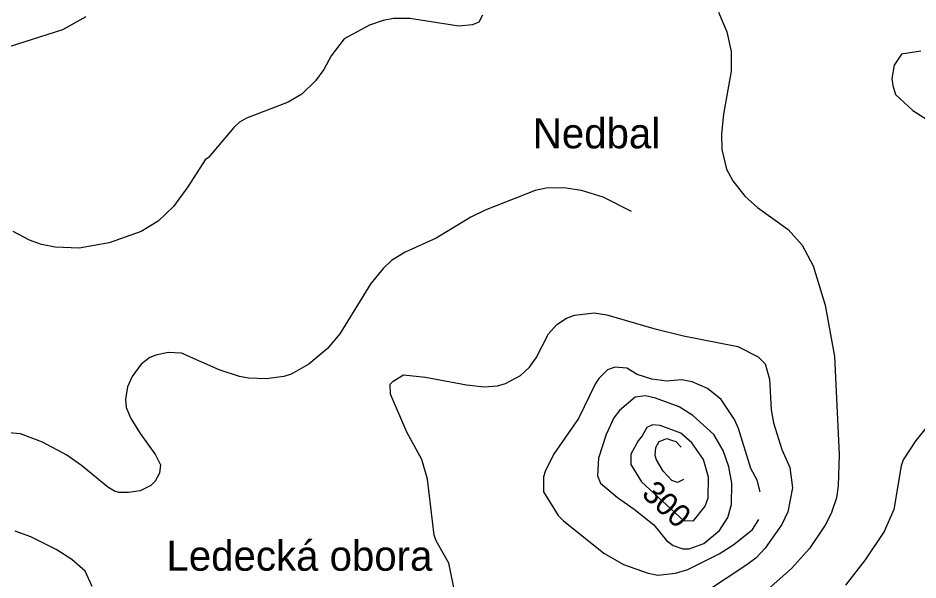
# Model space of a CAD drawing. Extents: x -662620 to -656370, y -1067090 to -1062990.
# Drawn here: x -662202 to -661678, y -1066171 to -1065844 of the extents above; entities that cross this region are included whole.
import ezdxf

# ---------------------------------------------------------------- set-up
doc = ezdxf.new("R2010")
doc.units = 0
for name, color, linetype in [('HRANICE_KATASTRÁLNÍHO_ÚZEMÍ', 7, 'Continuous'), ('MÍSTNÍ_NÁZVY', 7, 'Continuous'), ('VRSTEVNICE_ZDŮRAZNĚNÁ', 7, 'Continuous'), ('VRSTEVNICE_ZDŮRAZNĚNÁ_-_POPIS', 7, 'Continuous'), ('VRSTEVNICE_ZÁKLADNÍ', 7, 'Continuous')]:
    doc.layers.add(name, color=color, linetype=linetype)

msp = doc.modelspace()

# ---------------------------------------------------------------- linework, layer by layer
at = {"layer": 'HRANICE_KATASTRÁLNÍHO_ÚZEMÍ'}
msp.add_lwpolyline([(-662220.38, -1065864.43), (-662176.37, -1065850.47), (-662162.75, -1065842.94)], dxfattribs=at)
at = {"layer": 'VRSTEVNICE_ZDŮRAZNĚNÁ'}
for points in [[(-661676.86, -1065863.15), (-661687.99, -1065864.87), (-661692.27, -1065871.29), (-661693.56, -1065879), (-661693.13, -1065882.99), (-661691.56, -1065888.28)], [(-661691.56, -1065888.28), (-661681.42, -1065897.55), (-661661.58, -1065910.26)], [(-661670.29, -1066078.26), (-661679.71, -1066089.68), (-661686.99, -1066101.1), (-661688.13, -1066104.52), (-661692.56, -1066129.93), (-661698.12, -1066142.78), (-661709.26, -1066159.19), (-661720.68, -1066173.89)], [(-661800.47, -1066111.09), (-661803.32, -1066100.81), (-661810.17, -1066091.11), (-661816.45, -1066085.54), (-661828.44, -1066081.11), (-661833.01, -1066080.54), (-661836.34, -1066082.2), (-661839.01, -1066086.97), (-661841.43, -1066089.96), (-661845.57, -1066097.67), (-661845.57, -1066103.81), (-661839.44, -1066113.8), (-661814.88, -1066136.35), (-661809.11, -1066136.61), (-661802.32, -1066127.93), (-661800.61, -1066123.08), (-661800.47, -1066111.09)]]:
    msp.add_lwpolyline(points, dxfattribs=at)
at = {"layer": 'VRSTEVNICE_ZÁKLADNÍ'}
for points in [[(-661931.97, -1065842.23), (-661934.08, -1065846.14), (-661937.78, -1065847.83), (-661945.7, -1065848.46), (-661974.32, -1065844.17), (-661983.74, -1065844.03), (-661989.74, -1065845.17), (-661997.73, -1065848.02), (-662012.43, -1065855.87), (-662020, -1065865.87), (-662024.42, -1065873.86), (-662029.28, -1065880.43), (-662037.13, -1065888.13), (-662045.12, -1065892.84), (-662069.39, -1065902.12), (-662073.38, -1065904.41), (-662076.81, -1065907.55), (-662091.51, -1065924.96), (-662093.51, -1065926.39), (-662103.5, -1065942.09), (-662111.78, -1065953.51), (-662120.77, -1065962.07), (-662130.76, -1065968.07), (-662149.32, -1065974.63), (-662166.73, -1065977.77), (-662180.72, -1065977.2), (-662188.71, -1065975.63), (-662195.71, -1065973.21), (-662205.27, -1065968.07)], [(-661794.61, -1065840.46), (-661789.76, -1065851.88), (-661787.19, -1065863.3), (-661787.19, -1065874.72), (-661791.62, -1065899.84), (-661792.9, -1065911.26), (-661792.62, -1065920.39), (-661789.9, -1065931.81), (-661786.19, -1065938.66), (-661779.2, -1065947.51), (-661771.78, -1065954.08), (-661753.93, -1065966.92), (-661745.94, -1065976.06), (-661739.52, -1065988.05), (-661732.52, -1066010.89), (-661727.12, -1066040.89), (-661724.25, -1066097.96), (-661724.82, -1066116.23), (-661725.96, -1066123.08), (-661728.95, -1066132.21), (-661732.38, -1066139.07), (-661741.52, -1066152.63), (-661752.08, -1066164.33), (-661772.21, -1066182.17)], [(-661794.61, -1065840.46), (-661789.76, -1065851.88), (-661787.19, -1065863.3), (-661787.19, -1065874.72), (-661791.62, -1065899.84), (-661792.9, -1065911.26), (-661792.62, -1065920.39), (-661789.9, -1065931.81), (-661786.19, -1065938.66), (-661779.2, -1065947.51), (-661771.78, -1065954.08), (-661753.93, -1065966.92), (-661745.94, -1065976.06), (-661739.52, -1065988.05), (-661732.52, -1066010.89), (-661727.12, -1066040.89), (-661724.25, -1066097.96), (-661724.82, -1066116.23), (-661725.96, -1066123.08), (-661728.95, -1066132.21), (-661732.38, -1066139.07), (-661741.52, -1066152.63), (-661752.08, -1066164.33), (-661772.21, -1066182.17)], [(-661845.28, -1065956.37), (-661861.74, -1065948.03), (-661874.41, -1065944.23), (-661884.68, -1065942.66), (-661894.96, -1065942.95), (-661901.24, -1065944.23), (-661930.36, -1065955.65), (-661938.78, -1065959.79), (-661958.91, -1065972.06), (-661976.89, -1065980.06), (-661984.88, -1065985.05), (-661989.74, -1065989.62), (-661997.02, -1065998.33), (-662015, -1066027.59), (-662022.28, -1066036.15), (-662033.13, -1066045.29), (-662043.41, -1066051.14), (-662047.69, -1066052.57), (-662057.97, -1066053.85), (-662068.24, -1066053.42), (-662073.38, -1066052.57), (-662085.37, -1066048.57), (-662107.21, -1066038.87), (-662114.89, -1066038.53), (-662122.2, -1066040.01), (-662125.62, -1066041.43), (-662130.62, -1066045.29), (-662135.9, -1066052.43), (-662138.61, -1066058.56), (-662139.9, -1066065.7), (-662139.33, -1066070.55), (-662136.76, -1066076.98), (-662131.33, -1066085.68), (-662122.34, -1066098.1), (-662119.34, -1066103.95), (-662120.06, -1066108.81), (-662122.48, -1066113.37), (-662125.05, -1066115.94), (-662131.18, -1066119.06), (-662138.14, -1066120.12), (-662143.61, -1066119.94), (-662146.18, -1066119.23), (-662150.03, -1066116.94), (-662165.45, -1066104.24), (-662174.01, -1066098.24), (-662188.14, -1066090.68), (-662200.99, -1066085.97), (-662217.26, -1066084.54)], [(-661946.34, -1066186.6), (-661951.48, -1066161.19), (-661958.91, -1066148.2), (-661960.19, -1066144.78), (-661964.05, -1066112.23), (-661967.19, -1066100.81), (-661976.04, -1066084.83), (-661985.46, -1066062.84), (-661985.74, -1066056.99), (-661984.03, -1066055.14), (-661977.91, -1066051.61), (-661965.19, -1066052.85), (-661941.21, -1066057.28), (-661930.93, -1066058.56), (-661923.22, -1066057.99), (-661918.65, -1066056.56), (-661909.81, -1066051.85), (-661904.67, -1066047.14), (-661900.67, -1066041.72), (-661893.53, -1066027.73), (-661888.68, -1066022.31), (-661882.97, -1066018.6), (-661878.4, -1066016.88), (-661866.98, -1066015.46), (-661859.56, -1066016.6), (-661832.16, -1066024.59), (-661815.03, -1066028.87), (-661783.34, -1066035.01)], [(-661946.34, -1066186.6), (-661951.48, -1066161.19), (-661958.91, -1066148.2), (-661960.19, -1066144.78), (-661964.05, -1066112.23), (-661967.19, -1066100.81), (-661976.04, -1066084.83), (-661985.46, -1066062.84), (-661985.74, -1066056.99), (-661984.03, -1066055.14), (-661977.91, -1066051.61), (-661965.19, -1066052.85), (-661941.21, -1066057.28), (-661930.93, -1066058.56), (-661923.22, -1066057.99), (-661918.65, -1066056.56), (-661909.81, -1066051.85), (-661904.67, -1066047.14), (-661900.67, -1066041.72), (-661893.53, -1066027.73), (-661888.68, -1066022.31), (-661882.97, -1066018.6), (-661878.4, -1066016.88), (-661866.98, -1066015.46), (-661859.56, -1066016.6), (-661832.16, -1066024.59), (-661815.03, -1066028.87), (-661783.34, -1066035.01)], [(-661783.34, -1066035.01), (-661771.49, -1066041), (-661767.35, -1066045.14), (-661764.78, -1066054.14), (-661763.93, -1066071.98), (-661762.5, -1066079.4), (-661757.65, -1066094.96), (-661752.94, -1066105.38), (-661751.51, -1066117.37), (-661754.22, -1066131.36), (-661757.79, -1066138.64), (-661767.35, -1066152.34), (-661772.92, -1066158.19), (-661778.63, -1066162.47), (-661801.61, -1066177.61)], [(-661783.34, -1066035.01), (-661771.49, -1066041), (-661767.35, -1066045.14), (-661764.78, -1066054.14), (-661763.93, -1066071.98), (-661762.5, -1066079.4), (-661757.65, -1066094.96), (-661752.94, -1066105.38), (-661751.51, -1066117.37), (-661754.22, -1066131.36), (-661757.79, -1066138.64), (-661767.35, -1066152.34), (-661772.92, -1066158.19), (-661778.63, -1066162.47), (-661801.61, -1066177.61)], [(-661770.22, -1066119.59), (-661772.01, -1066112.94), (-661775.71, -1066105.98), (-661782.91, -1066082.83), (-661785.34, -1066077.55), (-661793.03, -1066065.79), (-661801.04, -1066059.42), (-661809.89, -1066055.56), (-661816.17, -1066054.42), (-661824.73, -1066055.28), (-661833.3, -1066054.14), (-661841.86, -1066051.42), (-661848, -1066047.57), (-661854.99, -1066047), (-661859.28, -1066048.71), (-661864.27, -1066053.57), (-661866.27, -1066056.56), (-661876.12, -1066076.98), (-661890.25, -1066097.24), (-661895.25, -1066107.24), (-661896.39, -1066110.95), (-661896.53, -1066119.65), (-661887.82, -1066133.36), (-661884.83, -1066136.5), (-661861.27, -1066155.34), (-661849.86, -1066161.9), (-661835.58, -1066167.04), (-661829.87, -1066168.18), (-661819.59, -1066167.04), (-661812.46, -1066164.9), (-661794.19, -1066155.77), (-661785.62, -1066150.34), (-661774.77, -1066141.64), (-661771.06, -1066135.78)], [(-661770.22, -1066119.59), (-661772.01, -1066112.94), (-661775.71, -1066105.98), (-661782.91, -1066082.83), (-661785.34, -1066077.55), (-661793.03, -1066065.79), (-661801.04, -1066059.42), (-661809.89, -1066055.56), (-661816.17, -1066054.42), (-661824.73, -1066055.28), (-661833.3, -1066054.14), (-661841.86, -1066051.42), (-661848, -1066047.57), (-661854.99, -1066047), (-661859.28, -1066048.71), (-661864.27, -1066053.57), (-661866.27, -1066056.56), (-661876.12, -1066076.98), (-661890.25, -1066097.24), (-661895.25, -1066107.24), (-661896.39, -1066110.95), (-661896.53, -1066119.65), (-661887.82, -1066133.36), (-661884.83, -1066136.5), (-661861.27, -1066155.34), (-661849.86, -1066161.9), (-661835.58, -1066167.04), (-661829.87, -1066168.18), (-661819.59, -1066167.04), (-661812.46, -1066164.9), (-661794.19, -1066155.77), (-661785.62, -1066150.34), (-661774.77, -1066141.64), (-661771.06, -1066135.78)], [(-661809.46, -1066075.26), (-661817.45, -1066070.12), (-661831.3, -1066065.13), (-661837.01, -1066063.7), (-661843, -1066064.56), (-661852.14, -1066072.26), (-661855.42, -1066076.55), (-661859.99, -1066086.25), (-661864.41, -1066099.96), (-661864.98, -1066110.23), (-661863.27, -1066114.52), (-661853.42, -1066122.94), (-661843.57, -1066129.65), (-661832.16, -1066138.92), (-661824.88, -1066148.06), (-661821.02, -1066150.91), (-661815.31, -1066152.77), (-661811.6, -1066152.77), (-661803.18, -1066149.63), (-661794.04, -1066142.06), (-661789.19, -1066134.5), (-661787.05, -1066127.08), (-661786.76, -1066114.52), (-661788.48, -1066105.09), (-661791.76, -1066095.67), (-661797.33, -1066086.25), (-661809.46, -1066075.26)], [(-661809.46, -1066075.26), (-661817.45, -1066070.12), (-661831.3, -1066065.13), (-661837.01, -1066063.7), (-661843, -1066064.56), (-661852.14, -1066072.26), (-661855.42, -1066076.55), (-661859.99, -1066086.25), (-661864.41, -1066099.96), (-661864.98, -1066110.23), (-661863.27, -1066114.52), (-661853.42, -1066122.94), (-661843.57, -1066129.65), (-661832.16, -1066138.92), (-661824.88, -1066148.06), (-661821.02, -1066150.91), (-661815.31, -1066152.77), (-661811.6, -1066152.77), (-661803.18, -1066149.63), (-661794.04, -1066142.06), (-661789.19, -1066134.5), (-661787.05, -1066127.08), (-661786.76, -1066114.52), (-661788.48, -1066105.09), (-661791.76, -1066095.67), (-661797.33, -1066086.25), (-661809.46, -1066075.26)], [(-661815.02, -1066112.44), (-661818.5, -1066114.13), (-661821.78, -1066112.97), (-661826.73, -1066107.66), (-661830.58, -1066101.1), (-661831.44, -1066098.53), (-661831.01, -1066093.82), (-661829.16, -1066090.39), (-661824.65, -1066088.67), (-661821.88, -1066089.54), (-661819.45, -1066090.39), (-661816.31, -1066093.68)], [(-661815.02, -1066112.44), (-661818.5, -1066114.13), (-661821.78, -1066112.97), (-661826.73, -1066107.66), (-661830.58, -1066101.1), (-661831.44, -1066098.53), (-661831.01, -1066093.82), (-661829.16, -1066090.39), (-661824.65, -1066088.67), (-661821.88, -1066089.54), (-661819.45, -1066090.39), (-661816.31, -1066093.68)], [(-662159.31, -1066174.75), (-662163.31, -1066165.9), (-662171.02, -1066159.05), (-662180.15, -1066153.2), (-662195, -1066145.92), (-662204.13, -1066142.49)], [(-662159.31, -1066174.75), (-662163.31, -1066165.9), (-662171.02, -1066159.05), (-662180.15, -1066153.2), (-662195, -1066145.92), (-662204.13, -1066142.49)]]:
    msp.add_lwpolyline(points, dxfattribs=at)

# ---------------------------------------------------------------- texts
at = {"layer": 'MÍSTNÍ_NÁZVY'}
for s, p in [('Nedbal', (-661902.67, -1065919.65)), ('Ledecká obora', (-662115.96, -1066165.56))]:
    msp.add_text(s, height=17.5, dxfattribs=at).set_placement(p)
at = {"layer": 'VRSTEVNICE_ZDŮRAZNĚNÁ_-_POPIS'}
msp.add_text('300', height=13.2, rotation=317.43, dxfattribs=at).set_placement((-661839.94, -1066121.65))

doc.saveas('drawing.dxf')
